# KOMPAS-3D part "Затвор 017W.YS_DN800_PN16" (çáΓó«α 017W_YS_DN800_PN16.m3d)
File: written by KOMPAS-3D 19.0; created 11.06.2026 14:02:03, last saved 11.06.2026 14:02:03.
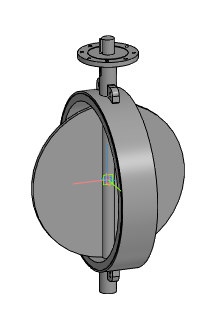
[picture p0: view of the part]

Document properties: Автор: Евгений; Полное имя файла: Z:\3.Личные\kachalov\001_3d для проектировщиков\x.x Тип 017W.Y(S) Затвор дисковый поворотный межфланцевый\_stp_Затвор 017W.YS_DN32-DN1200\Затвор 017W_YS_DN800_PN16.m3d

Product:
- Part/product: Затвор 017W.YS_DN800_PN16

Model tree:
1. Операция без истории:1  (labels: Затвор 017W.YS_DN800_PN16)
